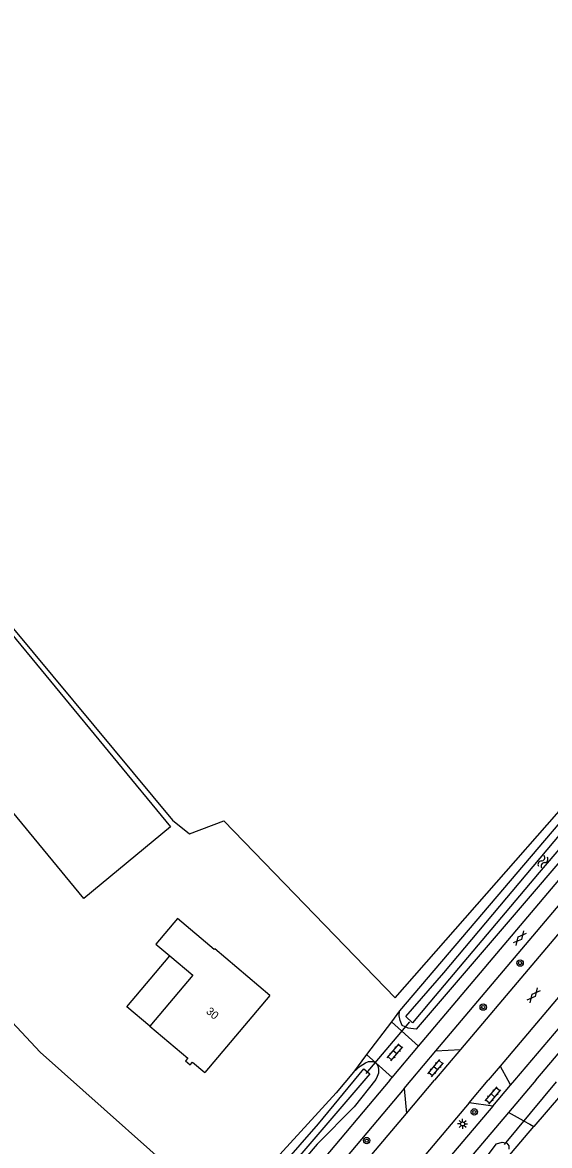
# Model space of a CAD drawing. Extents: x 135999 to 138000, y 396000 to 398501.
# Drawn here: x 136528.3 to 136594.2, y 397991.8 to 398132.2 of the extents above; entities that cross this region are included whole.
import ezdxf

# ---------------------------------------------------------------- set-up
doc = ezdxf.new("R2010")
doc.units = 0
for name, color, linetype in [('gg-afsc-draadraster', 7, 'Continuous'), ('gg-afsc-lijn draadraster', 7, 'Continuous'), ('gg-anno-huisnummerreeks BGT', 7, 'Continuous'), ('gg-bbg-gedigitaliseerde bebouwing', 7, 'Continuous'), ('gg-bbg-gedigitaliseerde bijgebouw', 7, 'Continuous'), ('gg-bbg-hoofdgebouw', 7, 'Continuous'), ('gg-bbg-luifel en loopbrug', 7, 'Continuous'), ('gg-knt-verharding', 7, 'Continuous'), ('gg-kntw-bovenkant insteek waterloop', 7, 'Continuous'), ('gg-kntw-waterlijn', 7, 'Continuous'), ('gg-kwrk-duiker nz buis', 7, 'Continuous'), ('gt-grn-groengrens', 7, 'Continuous'), ('gt-grn-vlakafsluiter', 7, 'Continuous'), ('gt-symb-boom', 7, 'Continuous'), ('gt-symb-gesloten verharding', 7, 'Continuous'), ('gt-symb-klinker verharding', 7, 'Continuous'), ('gt-symb-lichtmast', 7, 'Continuous'), ('gt-symb-watersymbool', 7, 'Continuous'), ('gx-grn-maaiveld', 7, 'Continuous')]:
    doc.layers.add(name, color=color, linetype=linetype)

# ---------------------------------------------------------------- blocks, each defined once
blk = doc.blocks.new('gt0-KL1')
at = {"layer": 'gt-symb-klinker verharding'}
for p, q in [((-1.15, 0.3), (1.15, 0.3)), ((-1, -0.3), (-1, 0.3)), ((-0.5, 0.3), (-0.5, 0.45)), ((0, -0.3), (0, 0.3)), ((0.5, 0.3), (0.5, 0.45)), ((1, -0.3), (1, 0.3)), ((-1.15, -0.3), (1.15, -0.3)), ((-0.5, -0.45), (-0.5, -0.3)), ((0.5, -0.45), (0.5, -0.3))]:
    blk.add_line(p, q, dxfattribs=at)
blk = doc.blocks.new('gt0-BOOM')
at = {"layer": 'gt-symb-boom'}
for radius in [0.4, 0.2]:
    blk.add_circle((0, 0), radius, dxfattribs=at)
blk = doc.blocks.new('gt0-GESVH1')
at = {"layer": 'gt-symb-gesloten verharding'}
for p, q in [((-0.99, -0.26), (0.01, 0.24)), ((0.01, -0.26), (-0.99, 0.24)), ((0.01, 0.24), (1.01, -0.26)), ((1.01, 0.24), (0.01, -0.26))]:
    blk.add_line(p, q, dxfattribs=at)
blk = doc.blocks.new('gt0-WA')
at = {"layer": 'gt-symb-watersymbool'}
for centre, start, end in [((-0.32, 0.02), 28.0725, 151.9275), ((0.43, 0.42), 208.0725, 331.9275), ((-0.32, -0.43), 28.0725, 151.9275), ((0.43, -0.03), 208.0725, 331.9275)]:
    blk.add_arc(centre, 0.425, start, end, dxfattribs=at)
blk = doc.blocks.new('gt0-LMAST')
at = {"layer": 'gt-symb-lichtmast'}
for p, q in [((-0.18, 0.17), (-0.45, 0.44)), ((-0.01, 0.25), (-0.01, 0.62)), ((0.17, 0.17), (0.44, 0.44)), ((-0.26, 0), (-0.63, 0)), ((-0.18, -0.18), (-0.45, -0.45)), ((-0.01, -0.25), (-0.01, -0.63)), ((0.44, -0.45), (0.17, -0.18)), ((0.24, 0), (0.62, 0))]:
    blk.add_line(p, q, dxfattribs=at)
blk.add_circle((-0.01, 0), 0.25, dxfattribs=at)

msp = doc.modelspace()

# ---------------------------------------------------------------- linework, layer by layer
at = {"layer": 'gg-afsc-draadraster'}
for points in [[(136547.06, 398032.49), (136549.18, 398030.77), (136553.47, 398032.42), (136563.56, 398022), (136574.88, 398010.3), (136607.79, 398047.69), (136616.26, 398057.26), (136645.88, 398091.09)], [(136535.04, 397962.26), (136552.22, 397984.2), (136530.53, 398003.52), (136520.61, 398014.1), (136517, 398010.87), (136513.24, 398014.78)]]:
    msp.add_lwpolyline(points, dxfattribs=at)
at = {"layer": 'gg-afsc-lijn draadraster'}
for points in [[(136547.06, 398032.49), (136549.18, 398030.77), (136553.47, 398032.42), (136563.56, 398022), (136574.88, 398010.3), (136607.79, 398047.69), (136616.26, 398057.26), (136645.88, 398091.09)], [(136535.04, 397962.26), (136552.22, 397984.2), (136530.53, 398003.52), (136520.61, 398014.1), (136517, 398010.87), (136513.24, 398014.78)]]:
    msp.add_lwpolyline(points, dxfattribs=at)
at = {"layer": 'gg-bbg-gedigitaliseerde bebouwing'}
for points in [[(136559.21, 398010.59), (136552.34, 398016.4), (136552.27, 398016.32), (136547.68, 398020.19), (136544.97, 398017.02), (136546.72, 398015.55)], [(136546.72, 398015.55), (136549.58, 398013.14), (136544.21, 398006.77)], [(136544.21, 398006.77), (136548.99, 398002.75), (136548.7, 398002.42), (136549.28, 398001.93), (136549.57, 398002.26), (136551.09, 398000.98)]]:
    msp.add_lwpolyline(points, dxfattribs=at)
at = {"layer": 'gg-bbg-gedigitaliseerde bijgebouw'}
msp.add_line((136518.24, 398066.27), (136546.8, 398031.64), dxfattribs=at)
msp.add_lwpolyline([(136546.8, 398031.64), (136535.97, 398022.7), (136507.4, 398057.33)], dxfattribs=at)
at = {"layer": 'gg-bbg-hoofdgebouw'}
msp.add_line((136559.21, 398010.59), (136551.09, 398000.98), dxfattribs=at)
at = {"layer": 'gg-bbg-luifel en loopbrug'}
msp.add_lwpolyline([(136544.21, 398006.77), (136541.36, 398009.17), (136546.72, 398015.55)], dxfattribs=at)
at = {"layer": 'gg-knt-verharding'}
for p, q in [((136579.98, 398003.66), (136612.61, 398042.28)), ((136574.42, 398007.29), (136571.31, 398003.22)), ((136574.42, 398007.29), (136577.83, 398004.25)), ((136574.54, 398000.35), (136577.83, 398004.25)), ((136576.89, 398000), (136579.98, 398003.66)), ((136583.07, 398003.86), (136579.81, 398000)), ((136579.98, 398003.66), (136583.07, 398003.86)), ((136571.31, 398003.22), (136574.54, 398000.35)), ((136588.02, 398001.74), (136586.54, 398000)), ((136588.02, 398001.74), (136589, 398000)), ((136574.24, 398000), (136543.45, 397963.57)), ((136574.24, 398000), (136574.54, 398000.35)), ((136576.02, 397998.98), (136576.89, 398000)), ((136576.3, 397995.86), (136579.81, 398000)), ((136584.15, 397997.17), (136586.54, 398000)), ((136587.13, 397996.78), (136589.34, 397999.38)), ((136589, 398000), (136589.34, 397999.38)), ((136592.5, 398000), (136589.08, 397995.97)), ((136589.34, 397999.38), (136589.87, 398000)), ((136576.02, 397998.98), (136545.24, 397962.55)), ((136576.02, 397998.98), (136576.3, 397995.86)), ((136587.13, 397996.78), (136584.15, 397997.17))]:
    msp.add_line(p, q, dxfattribs=at)
for points in [[(136577.83, 398004.25), (136614.94, 398048.15), (136686.64, 398130.48), (136688.12, 398132.15)], [(136592.5, 398000), (136611.17, 398021.99), (136625.02, 398038.05), (136676.67, 398097.38), (136679.24, 398100.45)], [(136589.87, 398000), (136611.11, 398024.99), (136669.7, 398092.41), (136675.02, 398098.62)], [(136659.09, 398084.05), (136621.69, 398041.08), (136602.56, 398018.96), (136588.02, 398001.74)], [(136613.7, 398039.67), (136599.97, 398023.85), (136583.07, 398003.86)], [(136584.15, 397997.17), (136539.05, 397943.79), (136526.11, 397928.2), (136523.23, 397924.77)], [(136587.13, 397996.78), (136562.73, 397968.07), (136556.48, 397961.52), (136551.02, 397955.37), (136548.53, 397951.66), (136544.55, 397946.63), (136524.9, 397923.36)], [(136589.08, 397995.97), (136565.61, 397968.32), (136560.57, 397962.82), (136556, 397958.13), (136552.84, 397954.46), (136549.16, 397949.16), (136546.1, 397945.36), (136526.37, 397922)], [(136546.96, 397961.24), (136554.87, 397970.5), (136576.3, 397995.86)]]:
    msp.add_lwpolyline(points, dxfattribs=at)
at = {"layer": 'gg-kntw-bovenkant insteek waterloop'}
for points in [[(136607.52, 398045.81), (136608.14, 398045.86), (136608.64, 398045.63), (136609.27, 398045.16), (136609.6, 398044.33), (136609.48, 398043.65), (136577.53, 398006.38), (136576.52, 398006.5), (136575.79, 398006.85), (136575.51, 398007.47), (136575.4, 398008.03), (136575.46, 398008.66)], [(136607.52, 398045.81), (136606.55, 398044.97), (136596.19, 398033.02), (136575.46, 398008.66)], [(136532.91, 397927.73), (136534.85, 397930.23), (136536.79, 397932.4), (136539.17, 397935.38), (136542.86, 397939.63), (136547.28, 397944.88), (136551.37, 397949.65), (136559.05, 397958.85), (136567.54, 397968.7), (136570.97, 397972.78), (136576.03, 397978.97), (136578.61, 397982.03), (136581.27, 397985.02), (136585.9, 397989.94), (136586.39, 397990.51), (136587.57, 397992.06), (136588.27, 397992.26), (136588.88, 397992.15), (136589.13, 397991.79), (136589.13, 397991.41)]]:
    msp.add_lwpolyline(points, dxfattribs=at)
at = {"layer": 'gg-kntw-waterlijn'}
for points in [[(136576.23, 398007.95), (136580.97, 398013.41), (136597.4, 398032.96), (136607.24, 398044.43), (136607.84, 398044.93), (136608.45, 398044.45), (136607.93, 398043.53), (136592.91, 398025.95), (136579.24, 398009.77), (136577.05, 398007.18), (136576.23, 398007.95)], [(136543.31, 397969.16), (136550.14, 397977.2), (136565.31, 397994.57), (136570.97, 398001.41), (136571.71, 398000.8), (136562.49, 397990.01), (136544.08, 397968.45), (136543.31, 397969.16)]]:
    msp.add_lwpolyline(points, dxfattribs=at)
at = {"layer": 'gg-kwrk-duiker nz buis'}
for p, q in [((136571.27, 398000.84), (136576.75, 398007.28)), ((136595.05, 397999.82), (136588.54, 397991.98))]:
    msp.add_line(p, q, dxfattribs=at)
at = {"layer": 'gt-grn-groengrens'}
for p, q in [((136680.94, 398097.41), (136592.22, 397994.23)), ((136590.95, 397994.93), (136589.08, 397995.97))]:
    msp.add_line(p, q, dxfattribs=at)
for points in [[(136590.95, 397994.93), (136591.72, 397994.51), (136592.22, 397994.23)], [(136536.24, 397928.3), (136550.86, 397945.45), (136592.22, 397994.23)]]:
    msp.add_lwpolyline(points, dxfattribs=at)
at = {"layer": 'gt-grn-vlakafsluiter'}
msp.add_line((136575.46, 398008.66), (136574.42, 398007.29), dxfattribs=at)
at = {"layer": 'gx-grn-maaiveld'}
msp.add_line((136571.31, 398003.22), (136569.69, 398001.03), dxfattribs=at)
for points in [[(136502.12, 398028.25), (136497.07, 398024.86), (136485.56, 398039.78), (136488.18, 398043.59), (136477.3, 398056.37), (136474.05, 398059.46), (136481.43, 398066.05), (136491.19, 398072.88), (136492, 398073.72), (136493.49, 398072.18), (136504.99, 398081.7), (136512.93, 398087.52), (136525.49, 398071.24), (136523.38, 398069.92), (136519.2, 398066.59), (136522.23, 398062.32), (136547.06, 398032.49)], [(136569.69, 398001.03), (136570.53, 398001.77), (136571.19, 398002.18), (136571.56, 398002.35), (136571.9, 398002.35), (136572.13, 398002.33), (136572.38, 398002.21), (136572.62, 398001.99), (136572.77, 398001.67), (136572.83, 398001.31), (136572.81, 398000.88), (136572.66, 398000.45), (136572.46, 398000.11), (136569.77, 397996.67), (136565.16, 397992), (136558.82, 397984.59), (136550.35, 397974.16), (136545.35, 397967.81), (136544.92, 397967.45)], [(136569.69, 398001.03), (136567.51, 397998.44), (136559.58, 397989.72), (136554.69, 397984.9), (136551, 397980.42), (136547.86, 397976.56), (136542.36, 397970.1), (136541.82, 397969.47)]]:
    msp.add_lwpolyline(points, dxfattribs=at)

# ---------------------------------------------------------------- block references
at = {"layer": 'gt-symb-boom'}
for p in [(136590.52, 398014.64), (136585.91, 398009.14), (136584.79, 397996.04), (136571.34, 397992.46)]:
    msp.add_blockref('gt0-BOOM', p, dxfattribs=at)
at = {"layer": 'gt-symb-gesloten verharding'}
for p, rotation in [((136590.47, 398017.76), 49.82757657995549), ((136592.2, 398010.61), 49.82757658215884)]:
    msp.add_blockref('gt0-GESVH1', p, dxfattribs=dict(at, rotation=rotation))
at = {"layer": 'gt-symb-klinker verharding'}
for p, rotation in [((136574.88, 398003.48), 49.7838186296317), ((136579.97, 398001.5), 49.827576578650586), ((136587.13, 397998.1), 49.82757657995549)]:
    msp.add_blockref('gt0-KL1', p, dxfattribs=dict(at, rotation=rotation))
at = {"layer": 'gt-symb-lichtmast'}
msp.add_blockref('gt0-LMAST', (136583.33, 397994.54), dxfattribs=at)
at = {"layer": 'gt-symb-watersymbool', "rotation": 61.76909817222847}
msp.add_blockref('gt0-WA', (136593.35, 398027.25), dxfattribs=at)

# ---------------------------------------------------------------- texts
at = {"layer": 'gg-anno-huisnummerreeks BGT'}
msp.add_text('30', height=1, rotation=319.8, dxfattribs=at).set_placement((136551.17, 398008.47))

doc.saveas('drawing.dxf')
